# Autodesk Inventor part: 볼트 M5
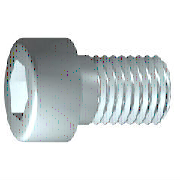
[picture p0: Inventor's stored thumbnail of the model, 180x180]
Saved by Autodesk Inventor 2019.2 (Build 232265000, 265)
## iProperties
IsCustomPart: 1
Created: 2012-02
Part Number: 볼트 M5
Material: 강철, 연강
Description: 6각머리 태핑 나사
Document SubType Name: Modeling
Standard: KS B 1003
Designer: mduedu
Standards Organization: KS
Language: ko-KR
Size Designation: M 5 x 16
Categories: <MemberInstance><Categories><Category DisplayName="조임쇠" InternalName="e4da775c-781d-43d5-af7c-5136215cf5a6" Mnemonic="FSTN"><Category DisplayName="볼트" InternalN
Density: 1 g/cm^3
Appearance: 강철
Author: mduedu
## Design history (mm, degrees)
sketch "스케치1"
  geometry: L1 (-1.167, 0)-(16, 0); L2 (16, 0)-(16, 2.5); L3 (16, 2.5)-(2, 2.5); L4 (2, 2.5)-(1.509, 2.5); L5 (1.509, 2.5)-(0, 2.5); L6 (0, 2.5)-(0, 4.25); L7 (0, 4.25)-(-5, 4.25); L8 (-5, 4.25)-(-5, 2.309); L9 (-5, 2.309)-(-2.5, 2.309); L10 (-2.5, 2.309)-(-1.167, 0); L11 (-9.2, 0)-(20.2, 0) reference; L12 (0, -0.85)-(0, 5.1) reference; L13 (2, 2.5)-(0, 2.5)
  constraints: 22 end point, 6 parallel, 2 collinear, 2 perpendicular, 1 horizontal, 1 point on line
  dimensions: "d1" = 14 distance from line of L3.end L2 (= GEL); "d2" = 0.49086 distance of L4.end L3.end (computed from GAL); "d3" = 5 distance between parallel lines of L8 L6 (= KOH); "d4" = 2.5 distance of L8.end L9.end (= INTI); "d5" = 60 deg angle of L10 L1; "d6" = 5 diameter of L3 L1 (= GD); "d7" = 5 diameter of L5 L1 (= BDM); "d8" = 4.6188 diameter of L9 L1 (= 1.1547 x SW); "d9" = 8.5 diameter of L7 L1 (= KOD); "d26" = 16 distance between parallel lines of L12 L2 (= NLG)
revolve "본체" sketch "스케치1" stored, may be unused: angle "d10" = 90 deg
sketch "스케치2"
  geometry: L1 (0, -5.95)-(0, 5.95) reference; L2 (-5.95, 0)-(5.95, 0) reference; L3 (2.309, 0)-(1.155, -2); L4 (1.155, -2)-(-1.155, -2); L5 (-1.155, -2)-(-2.309, 0); L6 (-2.309, 0)-(-1.155, 2); L7 (-1.155, 2)-(1.155, 2); L8 (1.155, 2)-(2.309, 0); 2 further points
  constraints: 12 end point, 1 coincident, 1 horizontal alignment, 1 point on line, 12 other
extrude "슬롯" join sketch "스케치2" stored distance "d11" = 10; taper "d12" = 0 deg
workplane "Work Plane1"
fillet "Fillet2" dims "d30" = 0.1 (= R)
body "Solid1"
fillet "모깎기1" dims "d17" = 0.5 (= RR)
feature "스레드" dims "d13" = 14 (= GEL), "d14" = 0
chamfer "모따기1" distance "d15" = 0.49076 (= -0.5 x SPD + 0.5 x GD); stored, may be unused: second distance "d16" = 0.49076 (= GUL), angle "d27" = 45 deg
other parameters: "GD" = 5 (= NND) [user parameter; used in 2 equation terms], "NLG" = 16 [user parameter; used in 1 equation term], "GEL" = 14 [user parameter; used in 2 equation terms], "KOD" = 8.5 [user parameter; used in 1 equation term], "KOH" = 5 [user parameter; used in 1 equation term], "INTI" = 2.5 [user parameter; used in 1 equation term], "GAL" = 0.49076 (= 0.61345 x PTC) [user parameter; used in 1 equation term], "GUL" = 0.49076 (= 0.61345 x PTC) [user parameter; used in 1 equation term], "BDM" = 5 (= NND) [user parameter; used in 1 equation term], "SW" = 4 [user parameter; used in 2 equation terms], "RR" = 0.5 [user parameter; used in 1 equation term], "SPD" = 4.01848 (= NND - 1.2269 x PTC) [user parameter; used in 1 equation term], "d19" = 0, "d28" = 0, "d29" = 0, "R" = 0.1 [user parameter; used in 1 equation term], "PHH" = 0.2 [user parameter], "GD1" = 4.01848 (= THREADDIA - 1.2269 x PTC) [user parameter], "THREADDIA" = 5 [user parameter; used in 1 equation term], "FAWI" = 45 deg [user parameter], "TPU" = 12.5 (computed from PTC) [user parameter], "PTC" = 0.8 [user parameter; used in 5 equation terms], "NND" = 5 [user parameter; used in 3 equation terms], "TOA" = 30 deg [user parameter], "E0" = 4.62 (= 1.155 x SW) [user parameter]
